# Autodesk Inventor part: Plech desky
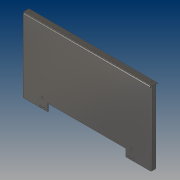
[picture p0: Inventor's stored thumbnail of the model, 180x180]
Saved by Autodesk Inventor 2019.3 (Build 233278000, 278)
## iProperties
Created: 2019-02
Part Number: Plech desky
Material: Nerezová ocel
Document SubType Name: Plech
Designer: B-hon
Density: 8 g/cm^3
Sheet Metal Rule: Výchozí_mm
Appearance: Ocel – leštěná
Author: B-hon
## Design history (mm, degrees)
node "Plocha1"
  sketch "Náčrt1"
    geometry: L1 (65, 0)-(635, 0) reference; L2 (700, 355)-(0, 355); L3 (65, 0)-(65, -45); L4 (65, -45)-(0, -45) reference; L5 (700, -45)-(635, -45) reference; L6 (635, -45)-(635, 0); L7 (0, 355)-(0, -45); L8 (700, 355)-(700, -45); 2 further points
    constraints: 16 end point, 4 horizontal, 2 vertical, 1 midpoint, 1 parallel, 1 other
    dimensions: "d1" = 355 distance of L2.end point (0, 0)
node "Obruba1"
node "Upravit přímo1"
node "Upravit přímo2"
sketch "Náčrt6"
  geometry: L1 (65, -5)-(65, -45) reference; L2 (65, -45)-(0, -45) reference; L3 (0, -45)-(0, 349) reference; 4 further points
  constraints: 1 horizontal alignment
  dimensions: "d71" = 21 distance of point (119, -38) point (98, -38); "d73" = 7 distance from line of L2 point (119, -38); "d74" = 10.5 horizontal distance of point (119, -38) point (108.5, 7); "d75" = 52 distance from line of L2 point (108.5, 7); "d155" = 98 distance from line of L3 point (98, -38)
hole "Díra4" sketch "Náčrt6" at (98, -38), (119, -38), (108.5, 7) diameter "d76" = 5.5; stored, may be unused: countersink angle "d80" = 90 deg, drill point angle "d82" = 118 deg; dims "d77" = 6, "d78" = 10.4, "d79" = 2, "d81" = 3 (= Tloušťka)
pattern_linear "Obdélníkové pole5" dims "d85" = 483
node "Obruba2"
node "Obruba3"
sketch "Náčrt13"
  geometry: L1 (0, 0)-(700, 0) reference; L2 (0, -29)-(0, 0) reference; 2 further points
  dimensions: "d137" = 10 distance from line of L1 point (20, -10); "d138" = 20 distance from line of point (20, -10) L2
hole "Díra7" sketch "Náčrt13" at (20, -10) diameter "d139" = 5.5; stored, may be unused: countersink angle "d143" = 90 deg, drill point angle "d145" = 0 deg; dims "d140" = 6, "d141" = 9.5, "d142" = 2, "d144" = 3 (= Tloušťka)
pattern_linear "Obdélníkové pole7" dims "d148" = 220
node "Těleso1"
feature "Deska1" dims "d8" = 3 (= Tloušťka)
sketch "Náčrt2"
  geometry: L1 through (350, 0) direction (-1, 0); L2 through (0, -17.5) direction (0, -1); L3 (0, -35)-(700, -35); L4 (700, -35)-(700, 0)
  constraints: 6 end point, 1 horizontal, 1 perpendicular, 1 vertical
feature "Deska2" dims "d8" = 3 (= Tloušťka), "d9" = 3 (= ŠířkaVýštipu), "d10" = 1.5 (= HloubkaVýštipu), "d11" = 6 (= MinimálníZbytek), "d12" = 3 (= PřechodovýPoloměr), "d13" = 35, "d14" = 90 deg, "d15" = 3 (= PoloměrOhybu), "d16" = 12 (= VelikostRohovéhoVýštipu), "d17" = 3 (= VelikostMezery), "d18" = 3 (= VelikostJacobihoPoloměru), "MezeraVystřižení" = 0.01
feature "Ohyb1" dims "d8" = 3 (= Tloušťka), "d9" = 3 (= ŠířkaVýštipu), "d10" = 1.5 (= HloubkaVýštipu), "d11" = 6 (= MinimálníZbytek), "d12" = 3 (= PřechodovýPoloměr), "d13" = 35, "d14" = 90 deg, "d15" = 3 (= PoloměrOhybu), "MezeraVystřižení" = 0.01
feature "Roh1" dims "d13" = 35, "d14" = 90 deg, "d16" = 12 (= VelikostRohovéhoVýštipu), "d17" = 3 (= VelikostMezery), "d18" = 3 (= VelikostJacobihoPoloměru)
sketch "Náčrt10"
  geometry: L1 through (197, 0) direction (-1, 0); L2 through (0, -12.5) direction (0, -1); L3 (0, -25)-(394, -25); L4 (394, -25)-(394, 0)
  constraints: 6 end point, 1 horizontal, 1 perpendicular, 1 vertical
feature "Deska3" dims "d8" = 3 (= Tloušťka), "d106" = 3 (= ŠířkaVýštipu), "d107" = 1.5 (= HloubkaVýštipu), "d108" = 6 (= MinimálníZbytek), "d109" = 3 (= PřechodovýPoloměr), "d110" = 25, "d111" = 90 deg, "d112" = 3 (= PoloměrOhybu), "d113" = 12 (= VelikostRohovéhoVýštipu), "d114" = 3 (= VelikostMezery), "d115" = 3 (= VelikostJacobihoPoloměru), "MezeraVystřižení" = 0.01
feature "Ohyb2" dims "d8" = 3 (= Tloušťka), "d106" = 3 (= ŠířkaVýštipu), "d107" = 1.5 (= HloubkaVýštipu), "d108" = 6 (= MinimálníZbytek), "d109" = 3 (= PřechodovýPoloměr), "d110" = 25, "d111" = 90 deg, "d112" = 3 (= PoloměrOhybu), "MezeraVystřižení" = 0.01
feature "Roh2" dims "d110" = 25, "d111" = 90 deg, "d113" = 12 (= VelikostRohovéhoVýštipu), "d114" = 3 (= VelikostMezery), "d115" = 3 (= VelikostJacobihoPoloměru)
sketch "Náčrt11"
  geometry: L1 through (197, 0) direction (-1, -6.78e-36); L2 through (0, -12.5) direction (-8.16e-33, -1); L3 (0, -25)-(394, -25); L4 (394, -25)-(394, 0)
  constraints: 6 end point, 1 horizontal, 1 perpendicular, 1 vertical
feature "Deska4" dims "d8" = 3 (= Tloušťka), "d116" = 3 (= ŠířkaVýštipu), "d117" = 1.5 (= HloubkaVýštipu), "d118" = 6 (= MinimálníZbytek), "d119" = 3 (= PřechodovýPoloměr), "d120" = 25, "d121" = 90 deg, "d122" = 3 (= PoloměrOhybu), "d123" = 12 (= VelikostRohovéhoVýštipu), "d124" = 3 (= VelikostMezery), "d125" = 3 (= VelikostJacobihoPoloměru), "MezeraVystřižení" = 0.01
feature "Ohyb3" dims "d8" = 3 (= Tloušťka), "d116" = 3 (= ŠířkaVýštipu), "d117" = 1.5 (= HloubkaVýštipu), "d118" = 6 (= MinimálníZbytek), "d119" = 3 (= PřechodovýPoloměr), "d120" = 25, "d121" = 90 deg, "d122" = 3 (= PoloměrOhybu), "MezeraVystřižení" = 0.01
feature "Roh3" dims "d120" = 25, "d121" = 90 deg, "d123" = 12 (= VelikostRohovéhoVýštipu), "d124" = 3 (= VelikostMezery), "d125" = 3 (= VelikostJacobihoPoloměru)
feature "Posunout1" dims "d56" = 5
feature "Posunout2" dims "d151" = 73
feature "Posunout3" dims "d154" = 73
other parameters: "Tloušťka" = 3 (derived), "KSoučinitel" = 4.4, "PoloměrOhybu" = 3 (= Tloušťka), "ŠířkaVýštipu" = 3 (= Tloušťka), "HloubkaVýštipu" = 1.5 (= 0.5 x Tloušťka), "VelikostRohovéhoVýštipu" = 12 (= 4 x Tloušťka), "MinimálníZbytek" = 6 (= 2 x Tloušťka), "PřechodovýPoloměr" = 3 (= PoloměrOhybu), "VelikostJacobihoPoloměru" = 3 (= PoloměrOhybu), "VelikostMezery" = 3 (= Tloušťka), "d54" = 0, "d55" = 0, "d149" = 0, "d150" = 0, "d152" = 0, "d153" = 0
